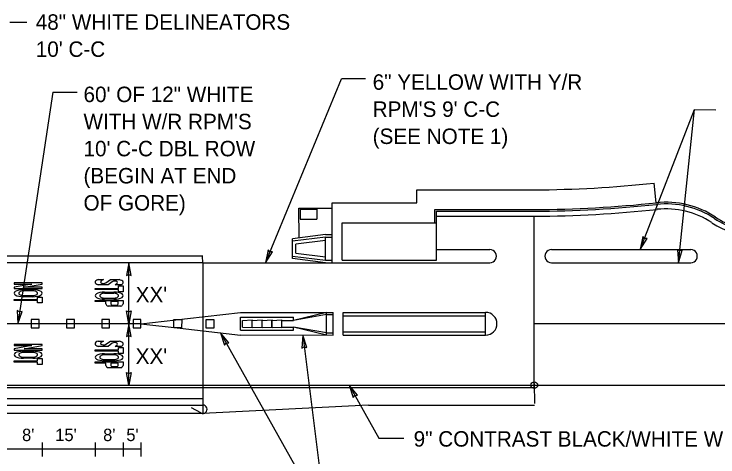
# Model space of a CAD drawing. Extents: x 583689 to 590775, y 1496016 to 1497365.
# Drawn here: x 587578.1 to 587896.7, y 1496243.3 to 1496443.8 of the extents above; entities that cross this region are included whole.
import ezdxf

# ---------------------------------------------------------------- set-up
doc = ezdxf.new("R2010")
doc.units = 0
for name, color, linetype in [('2', 7, 'Continuous'), ('21', 7, 'Continuous'), ('22', 7, 'Continuous'), ('28', 7, 'Continuous'), ('3', 7, 'Continuous'), ('41', 7, 'Continuous'), ('42', 7, 'Continuous'), ('46', 7, 'Continuous'), ('52', 7, 'Continuous'), ('PavtMessage', 7, 'Continuous'), ('TextLabel', 7, 'Continuous')]:
    doc.layers.add(name, color=color, linetype=linetype)

msp = doc.modelspace()

# ---------------------------------------------------------------- linework, layer by layer
at = {"layer": '2'}
for p, q in [((587868.77, 1496358.35), (587867.8, 1496367.29)), ((587760.33, 1496364.3), (587813.57, 1496364.31)), ((587760.33, 1496358.37), (587760.33, 1496364.3)), ((587722.07, 1496349.37), (587722.07, 1496358.37)), ((587722.07, 1496358.37), (587760.33, 1496358.37)), ((587707.07, 1496355.99), (587722.07, 1496356)), ((587707.08, 1496342.5), (587707.07, 1496355.99)), ((587768.57, 1496355.31), (587813.56, 1496355.31)), ((587768.57, 1496349.38), (587768.57, 1496355.3)), ((587769.32, 1496332.37), (587769.32, 1496354.56)), ((587769.32, 1496354.56), (587813.56, 1496354.56)), ((587769.32, 1496352.31), (587813.57, 1496352.31)), ((587813.57, 1496275.75), (587813.57, 1496352.31)), ((587722.07, 1496331.25), (587722.07, 1496349.37)), ((587726.57, 1496349.37), (587769.32, 1496349.38)), ((587726.57, 1496332.38), (587726.57, 1496349.37)), ((587719.07, 1496344), (587704.07, 1496342.13)), ((587719.07, 1496342.87), (587704.07, 1496340.99)), ((587704.07, 1496333.13), (587704.07, 1496342.13)), ((587719.07, 1496341.35), (587705.57, 1496339.67)), ((587719.07, 1496344), (587722.07, 1496344)), ((587719.07, 1496332.38), (587719.07, 1496342.88)), ((587719.07, 1496342.88), (587722.07, 1496342.88)), ((587705.57, 1496335.58), (587705.57, 1496339.67)), ((587705.57, 1496335.58), (587719.07, 1496333.9)), ((587769.32, 1496337.25), (587793.42, 1496337.25)), ((587704.07, 1496334.26), (587719.07, 1496332.38)), ((587719.07, 1496331.25), (587704.07, 1496333.13)), ((587719.07, 1496332.38), (587722.07, 1496332.39)), ((587726.57, 1496332.38), (587769.32, 1496332.37)), ((587663.57, 1496331.25), (587326.15, 1496331.25)), ((587663.57, 1496331.25), (587793.42, 1496331.25)), ((587663.58, 1496331.25), (587663.58, 1496275.75)), ((587656.54, 1496306.03), (587680.53, 1496308.76)), ((587680.53, 1496308.73), (587722.57, 1496308.75)), ((587680.53, 1496306.63), (587704.57, 1496306.63)), ((587680.53, 1496300.63), (587680.53, 1496306.63)), ((587719.57, 1496308.75), (587704.57, 1496305.13)), ((587719.57, 1496307.76), (587704.57, 1496305.13)), ((587704.57, 1496305.13), (587704.57, 1496306.63)), ((587719.57, 1496298.5), (587719.57, 1496308.75)), ((587719.57, 1496307.76), (587722.55, 1496307.76)), ((587722.57, 1496298.5), (587722.57, 1496308.75)), ((587727.07, 1496298.5), (587727.07, 1496308.75)), ((587727.07, 1496308.75), (587791.54, 1496308.75)), ((587727.07, 1496307.25), (587762.14, 1496307.25)), ((587762.14, 1496307.25), (587791.54, 1496307.25)), ((587791.54, 1496298.5), (587791.54, 1496308.75)), ((587635.53, 1496303.64), (587539.85, 1496303.64)), ((587635.53, 1496303.64), (587656.54, 1496306.03)), ((587635.53, 1496303.64), (587653.24, 1496301.62)), ((587681.44, 1496305.12), (587685.94, 1496305.37)), ((587681.44, 1496305.12), (587685.94, 1496305.37)), ((587681.44, 1496305.12), (587685.94, 1496305.37)), ((587681.44, 1496305.12), (587685.94, 1496305.37)), ((587681.44, 1496302.12), (587681.44, 1496305.13)), ((587681.44, 1496302.12), (587681.44, 1496305.13)), ((587681.44, 1496302.12), (587681.44, 1496305.13)), ((587681.44, 1496302.12), (587681.44, 1496305.13)), ((587681.44, 1496302.11), (587681.44, 1496305.13)), ((587681.44, 1496302.11), (587681.44, 1496305.13)), ((587681.44, 1496302.11), (587681.44, 1496305.13)), ((587681.44, 1496302.11), (587681.44, 1496305.13)), ((587681.44, 1496302.11), (587681.44, 1496305.13)), ((587681.44, 1496302.11), (587681.44, 1496305.13)), ((587681.44, 1496302.11), (587681.44, 1496305.13)), ((587681.44, 1496302.11), (587681.44, 1496305.13)), ((587681.44, 1496302.1), (587681.44, 1496305.12)), ((587681.44, 1496302.1), (587681.44, 1496305.12)), ((587681.44, 1496302.1), (587681.44, 1496305.12)), ((587681.44, 1496302.1), (587681.44, 1496305.12)), ((587685.9, 1496305.12), (587690.4, 1496305.38)), ((587685.9, 1496305.12), (587690.4, 1496305.38)), ((587685.9, 1496305.12), (587690.4, 1496305.38)), ((587685.9, 1496305.12), (587690.4, 1496305.38)), ((587685.9, 1496302.11), (587685.9, 1496305.12)), ((587685.9, 1496302.11), (587685.9, 1496305.12)), ((587685.9, 1496302.11), (587685.9, 1496305.12)), ((587685.9, 1496302.11), (587685.9, 1496305.12)), ((587685.91, 1496302.1), (587685.9, 1496305.12)), ((587685.91, 1496302.1), (587685.9, 1496305.12)), ((587685.91, 1496302.1), (587685.9, 1496305.12)), ((587685.91, 1496302.1), (587685.9, 1496305.12)), ((587685.91, 1496302.1), (587685.9, 1496305.12)), ((587685.91, 1496302.1), (587685.9, 1496305.12)), ((587685.91, 1496302.1), (587685.9, 1496305.12)), ((587685.91, 1496302.1), (587685.9, 1496305.12)), ((587685.94, 1496301.87), (587685.94, 1496305.37)), ((587685.94, 1496301.87), (587685.94, 1496305.37)), ((587685.94, 1496301.87), (587685.94, 1496305.37)), ((587685.94, 1496301.87), (587685.94, 1496305.37)), ((587690.36, 1496305.13), (587694.86, 1496305.38)), ((587690.36, 1496305.13), (587694.86, 1496305.38)), ((587690.36, 1496302.11), (587690.36, 1496305.13)), ((587690.36, 1496302.11), (587690.36, 1496305.13)), ((587690.36, 1496302.11), (587690.36, 1496305.13)), ((587690.36, 1496302.11), (587690.36, 1496305.13)), ((587690.36, 1496302.11), (587690.36, 1496305.13)), ((587690.36, 1496302.11), (587690.36, 1496305.13)), ((587690.36, 1496302.11), (587690.36, 1496305.13)), ((587690.36, 1496302.11), (587690.36, 1496305.13)), ((587690.4, 1496301.88), (587690.4, 1496305.38)), ((587690.4, 1496301.88), (587690.4, 1496305.38)), ((587690.4, 1496301.88), (587690.4, 1496305.38)), ((587690.4, 1496301.88), (587690.4, 1496305.38)), ((587694.82, 1496305.13), (587699.32, 1496305.38)), ((587694.82, 1496302.11), (587694.82, 1496305.13)), ((587694.82, 1496302.11), (587694.82, 1496305.13)), ((587694.86, 1496301.88), (587694.86, 1496305.38)), ((587694.86, 1496301.88), (587694.86, 1496305.38)), ((587699.32, 1496301.88), (587699.32, 1496305.38)), ((587699.32, 1496305.13), (587704.57, 1496305.13)), ((587813.57, 1496303.79), (588039.9, 1496303.8)), ((587653.24, 1496301.62), (587680.53, 1496298.5)), ((587680.53, 1496300.63), (587704.57, 1496300.63)), ((587681.44, 1496302.1), (587685.94, 1496301.87)), ((587681.44, 1496302.1), (587685.94, 1496301.87)), ((587681.44, 1496302.1), (587685.94, 1496301.87)), ((587681.44, 1496302.1), (587685.94, 1496301.87)), ((587685.9, 1496302.11), (587690.4, 1496301.88)), ((587685.9, 1496302.11), (587690.4, 1496301.88)), ((587685.9, 1496302.11), (587690.4, 1496301.88)), ((587685.9, 1496302.11), (587690.4, 1496301.88)), ((587690.36, 1496302.11), (587694.86, 1496301.88)), ((587690.36, 1496302.11), (587694.86, 1496301.88)), ((587694.82, 1496302.11), (587699.32, 1496301.88)), ((587699.32, 1496302.13), (587704.57, 1496302.13)), ((587704.57, 1496300.63), (587704.57, 1496302.19)), ((587719.57, 1496298.5), (587704.57, 1496302.13)), ((587719.57, 1496299.5), (587704.57, 1496302.13)), ((587727.07, 1496300), (587762.46, 1496300)), ((587762.46, 1496300), (587791.54, 1496300)), ((587680.53, 1496298.52), (587722.57, 1496298.5)), ((587719.57, 1496299.5), (587722.58, 1496299.5)), ((587727.07, 1496298.5), (587791.54, 1496298.5)), ((587326.15, 1496274.75), (587663.58, 1496274.75)), ((587387.69, 1496275.75), (587663.57, 1496275.75)), ((587663.57, 1496275.75), (587774.7, 1496275.75)), ((587663.57, 1496275.75), (588039.9, 1496275.75)), ((587663.58, 1496274.75), (587813.57, 1496274.75)), ((587774.7, 1496275.75), (587813.57, 1496275.76)), ((587813.57, 1496274.75), (587813.57, 1496275.75)), ((587813.57, 1496274.75), (587813.57, 1496275.75))]:
    msp.add_line(p, q, dxfattribs=at)
for points in [[(587585.91, 1496301.74), (587589.46, 1496301.74), (587589.47, 1496305.54), (587585.91, 1496305.54)], [(587601.86, 1496301.74), (587605.41, 1496301.74), (587605.42, 1496305.54), (587601.86, 1496305.54)], [(587617.81, 1496301.74), (587621.36, 1496301.74), (587621.36, 1496305.54), (587617.81, 1496305.54)], [(587631.98, 1496301.74), (587635.53, 1496301.74), (587635.54, 1496305.54), (587631.98, 1496305.54)], [(587653.97, 1496301.77), (587650.42, 1496301.77), (587650.42, 1496305.56), (587653.98, 1496305.56)], [(587668.55, 1496301.67), (587665, 1496301.67), (587665, 1496305.47), (587668.55, 1496305.47)]]:
    msp.add_lwpolyline(points, close=True, dxfattribs=at)
for centre, radius, start, end in [((587811.34, 1496889.63), 525.38, 270.2388, 276.1694), ((587811.34, 1496889.68), 534.38, 270.2375, 276.1752), ((587811.34, 1496889.68), 535.13, 270.2375, 276.1752), ((587873.18, 1496318.14), 40.5, 56.4357, 96.1704), ((587873.18, 1496318.14), 39.75, 56.4357, 96.1704), ((587811.34, 1496889.68), 537.38, 270.2375, 276.1752), ((587873.18, 1496318.14), 37.5, 56.4357, 96.1704), ((587914.65, 1496380.63), 35.25, 236.4357, 253.0681), ((587914.65, 1496380.63), 34.5, 236.4357, 254.5578), ((587914.65, 1496380.63), 37.5, 236.4357, 269.7206), ((587791.54, 1496303.63), 5.13, 269.9999, 89.9999)]:
    msp.add_arc(centre, radius, start, end, dxfattribs=at)
at = {"layer": '21'}
for p, q in [((587583.82, 1496440.04), (587576.23, 1496440.04)), ((587691.86, 1496331.25), (587726.28, 1496414.56)), ((587737.12, 1496414.56), (587726.28, 1496414.56)), ((587595.7, 1496408.42), (587579.78, 1496303.64)), ((587595.7, 1496408.42), (587606.68, 1496408.42)), ((587861.54, 1496337.25), (587886.12, 1496400.69)), ((587878.81, 1496331.25), (587886.12, 1496400.69)), ((587886.12, 1496400.69), (587895.69, 1496400.51)), ((587630.11, 1496303.64), (587630.11, 1496331.25)), ((587630.11, 1496275.75), (587630.11, 1496303.64)), ((587671.49, 1496299.53), (587719.42, 1496214.25)), ((587708.8, 1496298.51), (587719.42, 1496214.25)), ((587729.78, 1496275.75), (587743.24, 1496251.8)), ((587590.88, 1496249.83), (587590.88, 1496243.54)), ((587614.8, 1496249.83), (587614.8, 1496243.54)), ((587627.56, 1496249.83), (587627.56, 1496243.54)), ((587635.53, 1496249.83), (587635.53, 1496243.54)), ((587743.24, 1496251.8), (587754.45, 1496251.8)), ((587635.53, 1496246.88), (587541.44, 1496246.88))]:
    msp.add_line(p, q, dxfattribs=at)
at = {"layer": '22'}
for q in [(587663.57, 1496263), (587813.6, 1496266.76)]:
    msp.add_line((587738.57, 1496266.76), q, dxfattribs=at)
at = {"layer": '28'}
msp.add_circle((587813.57, 1496275.76), 1.5, dxfattribs=at)
at = {"layer": '3'}
for p, q in [((587821.35, 1496337.25), (587884.35, 1496337.25)), ((587821.35, 1496331.25), (587884.35, 1496331.25))]:
    msp.add_line(p, q, dxfattribs=at)
for centre, start, end in [((587793.42, 1496334.25), 269.9999, 90.0236), ((587821.35, 1496334.25), 89.9764, 270.0001), ((587884.35, 1496334.25), 269.9999, 90.0236)]:
    msp.add_arc(centre, 3, start, end, dxfattribs=at)
at = {"layer": '41'}
for p, q in [((587326.15, 1496275.75), (587663.57, 1496275.75)), ((587663.57, 1496275.75), (587774.7, 1496275.75)), ((587774.7, 1496275.75), (587813.57, 1496275.75))]:
    msp.add_line(p, q, dxfattribs=at)
at = {"layer": '42'}
for p, q in [((587663.57, 1496334.25), (587326.15, 1496334.25)), ((587663.58, 1496331.25), (587663.38, 1496334.25)), ((587663.57, 1496275.75), (587663.57, 1496263)), ((587813.57, 1496276.51), (587813.6, 1496267.51)), ((587326.15, 1496269.75), (587663.57, 1496269.75)), ((587663.57, 1496263), (587326.15, 1496263))]:
    msp.add_line(p, q, dxfattribs=at)
at = {"layer": '46'}
for p, q in [((587707.63, 1496355.47), (587715.13, 1496355.47)), ((587707.63, 1496355.47), (587707.63, 1496350.97)), ((587715.13, 1496355.47), (587715.13, 1496350.97)), ((587707.63, 1496350.97), (587715.13, 1496350.97)), ((587326.15, 1496266.75), (587663.57, 1496266.75)), ((587662.7, 1496263.22), (587658.49, 1496265.5))]:
    msp.add_line(p, q, dxfattribs=at)
msp.add_arc((587663.57, 1496264.88), 1.88, 242.305, 90.004, dxfattribs=at)
at = {"layer": '52'}
for p, q in [((587862.63, 1496343.05), (587861.54, 1496337.25)), ((587861.54, 1496337.25), (587864.68, 1496342.25)), ((587863.48, 1496342.25), (587862.63, 1496343.05)), ((587864.68, 1496342.25), (587863.48, 1496342.25)), ((587693.08, 1496337.02), (587691.86, 1496331.25)), ((587691.86, 1496331.25), (587695.11, 1496336.18)), ((587693.91, 1496336.21), (587693.08, 1496337.02)), ((587695.11, 1496336.18), (587693.91, 1496336.21)), ((587879.37, 1496336.58), (587878.34, 1496337.13)), ((587878.34, 1496337.13), (587878.81, 1496331.25)), ((587878.81, 1496331.25), (587880.53, 1496336.9)), ((587880.53, 1496336.9), (587879.37, 1496336.58)), ((587630.11, 1496331.25), (587628.99, 1496325.45)), ((587631.19, 1496325.45), (587630.11, 1496331.25)), ((587628.99, 1496325.45), (587630.11, 1496325.89)), ((587630.11, 1496325.89), (587631.19, 1496325.45)), ((587580.59, 1496308.94), (587579.59, 1496309.54)), ((587579.59, 1496309.54), (587579.78, 1496303.64)), ((587579.78, 1496303.64), (587581.76, 1496309.21)), ((587581.76, 1496309.21), (587580.59, 1496308.94)), ((587630.11, 1496303.64), (587628.99, 1496309.44)), ((587628.99, 1496309.44), (587630.11, 1496309)), ((587630.11, 1496309), (587631.19, 1496309.44)), ((587631.19, 1496309.44), (587630.11, 1496303.64)), ((587630.11, 1496303.64), (587628.99, 1496297.84)), ((587631.19, 1496297.84), (587630.11, 1496303.64)), ((587628.99, 1496297.84), (587630.11, 1496298.28)), ((587630.11, 1496298.28), (587631.19, 1496297.84)), ((587671.49, 1496299.53), (587673.35, 1496293.93)), ((587675.27, 1496295.01), (587671.49, 1496299.53)), ((587708.8, 1496298.51), (587708.42, 1496292.61)), ((587710.6, 1496292.89), (587708.8, 1496298.51)), ((587673.35, 1496293.93), (587674.12, 1496294.86)), ((587674.12, 1496294.86), (587675.27, 1496295.01)), ((587708.42, 1496292.61), (587709.47, 1496293.19)), ((587709.47, 1496293.19), (587710.6, 1496292.89)), ((587630.11, 1496275.75), (587628.99, 1496281.55)), ((587628.99, 1496281.55), (587630.11, 1496281.11)), ((587630.11, 1496281.11), (587631.19, 1496281.55)), ((587631.19, 1496281.55), (587630.11, 1496275.75)), ((587729.78, 1496275.75), (587731.64, 1496270.15)), ((587733.56, 1496271.23), (587729.78, 1496275.75)), ((587732.4, 1496271.08), (587733.56, 1496271.23)), ((587731.64, 1496270.15), (587732.4, 1496271.08))]:
    msp.add_line(p, q, dxfattribs=at)
at = {"layer": 'PavtMessage'}
for p, q in [((587616.24, 1496323.63), (587618.56, 1496323.63)), ((587618.56, 1496323.63), (587617.56, 1496322.97)), ((587619.7, 1496322.18), (587621.75, 1496323.63)), ((587622.55, 1496322.66), (587620.71, 1496321.24)), ((587621.75, 1496323.63), (587625.66, 1496323.63)), ((587590.88, 1496322.11), (587578.12, 1496322.11)), ((587578.12, 1496322.11), (587578.12, 1496321.57)), ((587578.12, 1496321.57), (587586.1, 1496321.57)), ((587586.1, 1496321.57), (587578.12, 1496320.11)), ((587578.12, 1496320.11), (587578.12, 1496319.58)), ((587578.12, 1496319.58), (587590.88, 1496319.58)), ((587582.37, 1496319.05), (587586.63, 1496319.05)), ((587582.75, 1496320.11), (587590.88, 1496321.57)), ((587590.88, 1496320.11), (587582.75, 1496320.11)), ((587590.88, 1496321.57), (587590.88, 1496322.11)), ((587590.88, 1496319.58), (587590.88, 1496320.11)), ((587614.8, 1496319.11), (587614.8, 1496319.64)), ((587614.8, 1496319.64), (587625.43, 1496319.64)), ((587625.43, 1496319.11), (587614.8, 1496319.11)), ((587620.71, 1496321.24), (587616.24, 1496321.24)), ((587623.85, 1496321.24), (587624.77, 1496321.93)), ((587626.48, 1496321.24), (587623.85, 1496321.24)), ((587625.43, 1496320.71), (587627.56, 1496320.71)), ((587625.43, 1496319.64), (587625.43, 1496320.71)), ((587625.43, 1496318.05), (587625.43, 1496319.11)), ((587627.56, 1496320.71), (587627.56, 1496318.05)), ((587586.63, 1496318.52), (587582.37, 1496318.52)), ((587582.37, 1496316.39), (587586.63, 1496316.39)), ((587586.63, 1496315.86), (587582.37, 1496315.86)), ((587619.05, 1496317.92), (587623.31, 1496317.92)), ((587623.31, 1496317.38), (587619.05, 1496317.38)), ((587627.56, 1496318.05), (587625.43, 1496318.05)), ((587578.12, 1496314.12), (587578.12, 1496314.65)), ((587578.12, 1496314.65), (587588.75, 1496314.65)), ((587588.75, 1496314.12), (587578.12, 1496314.12)), ((587588.75, 1496315.72), (587590.88, 1496315.72)), ((587588.75, 1496314.65), (587588.75, 1496315.72)), ((587588.75, 1496313.06), (587588.75, 1496314.12)), ((587590.88, 1496313.06), (587588.75, 1496313.06)), ((587590.88, 1496315.72), (587590.88, 1496313.06)), ((587614.8, 1496314.19), (587627.56, 1496314.19)), ((587614.8, 1496313.66), (587614.8, 1496314.19)), ((587619.59, 1496313.66), (587614.8, 1496313.66)), ((587619.05, 1496315.26), (587623.31, 1496315.26)), ((587623.31, 1496314.73), (587619.05, 1496314.73)), ((587619.59, 1496312.65), (587619.59, 1496313.66)), ((587625.17, 1496313.66), (587621.98, 1496313.66)), ((587621.98, 1496313.66), (587621.98, 1496312.6)), ((587625.17, 1496312.6), (587625.17, 1496313.66)), ((587627.56, 1496314.19), (587627.56, 1496312.65)), ((587626.49, 1496311.54), (587620.65, 1496311.54)), ((587622.38, 1496312.07), (587624.76, 1496312.07)), ((587590.88, 1496294.22), (587578.12, 1496294.22)), ((587578.12, 1496294.22), (587578.12, 1496293.69)), ((587578.12, 1496293.69), (587586.1, 1496293.69)), ((587586.1, 1496293.69), (587578.12, 1496292.22)), ((587582.75, 1496292.22), (587590.88, 1496293.69)), ((587590.88, 1496293.69), (587590.88, 1496294.22)), ((587616.24, 1496295.74), (587618.56, 1496295.74)), ((587618.56, 1496295.74), (587617.56, 1496295.08)), ((587619.7, 1496294.29), (587621.75, 1496295.74)), ((587622.55, 1496294.77), (587620.71, 1496293.35)), ((587621.75, 1496295.74), (587625.66, 1496295.74)), ((587623.85, 1496293.35), (587624.77, 1496294.05)), ((587578.12, 1496292.22), (587578.12, 1496291.69)), ((587578.12, 1496291.69), (587590.88, 1496291.69)), ((587582.37, 1496291.16), (587586.63, 1496291.16)), ((587586.63, 1496290.63), (587582.37, 1496290.63)), ((587590.88, 1496292.22), (587582.75, 1496292.22)), ((587590.88, 1496291.69), (587590.88, 1496292.22)), ((587614.8, 1496291.22), (587614.8, 1496291.76)), ((587614.8, 1496291.76), (587625.43, 1496291.76)), ((587625.43, 1496291.22), (587614.8, 1496291.22)), ((587620.71, 1496293.35), (587616.24, 1496293.35)), ((587626.48, 1496293.35), (587623.85, 1496293.35)), ((587625.43, 1496292.82), (587627.56, 1496292.82)), ((587625.43, 1496291.76), (587625.43, 1496292.82)), ((587625.43, 1496290.16), (587625.43, 1496291.22)), ((587627.56, 1496292.82), (587627.56, 1496290.16)), ((587582.37, 1496288.5), (587586.63, 1496288.5)), ((587586.63, 1496287.97), (587582.37, 1496287.97)), ((587588.75, 1496287.83), (587590.88, 1496287.83)), ((587588.75, 1496286.77), (587588.75, 1496287.83)), ((587590.88, 1496287.83), (587590.88, 1496285.17)), ((587619.05, 1496290.03), (587623.31, 1496290.03)), ((587623.31, 1496289.5), (587619.05, 1496289.5)), ((587619.05, 1496287.37), (587623.31, 1496287.37)), ((587627.56, 1496290.16), (587625.43, 1496290.16)), ((587578.12, 1496286.24), (587578.12, 1496286.77)), ((587578.12, 1496286.77), (587588.75, 1496286.77)), ((587588.75, 1496286.24), (587578.12, 1496286.24)), ((587588.75, 1496285.17), (587588.75, 1496286.24)), ((587590.88, 1496285.17), (587588.75, 1496285.17)), ((587614.8, 1496286.31), (587627.56, 1496286.31)), ((587614.8, 1496285.77), (587614.8, 1496286.31)), ((587619.59, 1496285.77), (587614.8, 1496285.77)), ((587623.31, 1496286.84), (587619.05, 1496286.84)), ((587619.59, 1496284.76), (587619.59, 1496285.77)), ((587625.17, 1496285.77), (587621.98, 1496285.77)), ((587621.98, 1496285.77), (587621.98, 1496284.71)), ((587622.38, 1496284.18), (587624.76, 1496284.18)), ((587625.17, 1496284.71), (587625.17, 1496285.77)), ((587627.56, 1496286.31), (587627.56, 1496284.76)), ((587626.49, 1496283.65), (587620.65, 1496283.65))]:
    msp.add_line(p, q, dxfattribs=at)
for centre, major_axis, ratio, start_param, end_param in [((587619.05, 1496322.43), (-4.25, 0), 0.375, 5.435123, 7.131247), ((587618.61, 1496322.57), (1.33, 0), 0.5, 2.490106, 5.666015), ((587623.66, 1496322.3), (1.33, 0), 0.5, 5.699287, 8.851109), ((587623.31, 1496322.3), (4.25, 0), 0.375, 5.553458, 7.268296), ((587582.37, 1496317.45), (4.25, 0), 0.375, 1.570796, 4.712389), ((587586.63, 1496317.45), (4.25, 0), 0.375, 4.712389, 7.853982), ((587582.37, 1496317.45), (2.13, 0), 0.5, 1.570796, 4.712389), ((587586.63, 1496317.45), (2.13, 0), 0.5, 4.712389, 7.853982), ((587619.05, 1496316.32), (4.25, 0), 0.375, 1.570796, 4.712389), ((587619.05, 1496316.32), (2.13, 0), 0.5, 1.570796, 4.712389), ((587623.31, 1496316.32), (4.25, 0), 0.375, 4.712389, 7.853982), ((587623.31, 1496316.32), (2.13, 0), 0.5, 4.712389, 7.853982), ((587623.57, 1496313.66), (4.25, 0), 0.6875, 3.497014, 3.955933), ((587623.57, 1496313.66), (4.25, 0), 0.6875, 5.468845, 5.927764), ((587623.57, 1496312.6), (1.59, 0), 0.5, 3.141593, 3.87132), ((587623.57, 1496312.6), (1.59, 0), 0.5, 5.553458, 6.283185), ((587619.05, 1496294.55), (-4.25, 0), 0.375, 5.435123, 7.131247), ((587618.61, 1496294.68), (1.33, 0), 0.5, 2.490106, 5.666015), ((587623.66, 1496294.41), (1.33, 0), 0.5, 5.699287, 8.851109), ((587623.31, 1496294.41), (4.25, 0), 0.375, 5.553458, 7.268296), ((587582.37, 1496289.57), (4.25, 0), 0.375, 1.570796, 4.712389), ((587582.37, 1496289.57), (2.13, 0), 0.5, 1.570796, 4.712389), ((587586.63, 1496289.57), (4.25, 0), 0.375, 4.712389, 7.853982), ((587586.63, 1496289.57), (2.13, 0), 0.5, 4.712389, 7.853982), ((587619.05, 1496288.43), (4.25, 0), 0.375, 1.570796, 4.712389), ((587619.05, 1496288.43), (2.13, 0), 0.5, 1.570796, 4.712389), ((587623.31, 1496288.43), (4.25, 0), 0.375, 4.712389, 7.853982), ((587623.31, 1496288.43), (2.13, 0), 0.5, 4.712389, 7.853982), ((587623.57, 1496285.77), (4.25, 0), 0.6875, 3.497014, 3.955933), ((587623.57, 1496284.71), (1.59, 0), 0.5, 3.141593, 3.87132), ((587623.57, 1496284.71), (1.59, 0), 0.5, 5.553458, 6.283185), ((587623.57, 1496285.77), (4.25, 0), 0.6875, 5.468845, 5.927764)]:
    msp.add_ellipse(centre, major_axis=major_axis, ratio=ratio, start_param=start_param, end_param=end_param, dxfattribs=at)

# ---------------------------------------------------------------- texts
at = {"layer": '21'}
for s, p in [('48" WHITE DELINEATORS', (587587.93, 1496436.74)), ("10' C-C", (587587.93, 1496424.47)), ('6" YELLOW WITH Y/R ', (587740.42, 1496409.57)), ('60\' OF 12" WHITE', (587609.55, 1496403.98)), ("RPM'S 9' C-C", (587740.42, 1496397.29)), ("WITH W/R RPM'S", (587609.55, 1496391.7)), ('(SEE NOTE 1)', (587740.42, 1496385.01)), ("10' C-C DBL ROW", (587609.55, 1496379.43)), ('(BEGIN AT END', (587609.55, 1496367.15)), ('OF GORE)', (587609.55, 1496354.87)), ('9" CONTRAST BLACK/WHITE WITH W/R', (587758.97, 1496247.96))]:
    msp.add_text(s, height=7, dxfattribs=at).set_placement(p)
for p in [(587633.17, 1496313.3), (587633.17, 1496285.41)]:
    msp.add_text("XX'", height=7, rotation=0.2102, dxfattribs=at).set_placement(p)
at = {"layer": 'TextLabel'}
for s, p in [("8'", (587581.74, 1496250.47)), ("15'", (587596.75, 1496250.47)), ("8'", (587618.42, 1496250.47)), ("5'", (587628.92, 1496250.47))]:
    msp.add_text(s, height=5.582, dxfattribs=at).set_placement(p)

doc.saveas('drawing.dxf')
